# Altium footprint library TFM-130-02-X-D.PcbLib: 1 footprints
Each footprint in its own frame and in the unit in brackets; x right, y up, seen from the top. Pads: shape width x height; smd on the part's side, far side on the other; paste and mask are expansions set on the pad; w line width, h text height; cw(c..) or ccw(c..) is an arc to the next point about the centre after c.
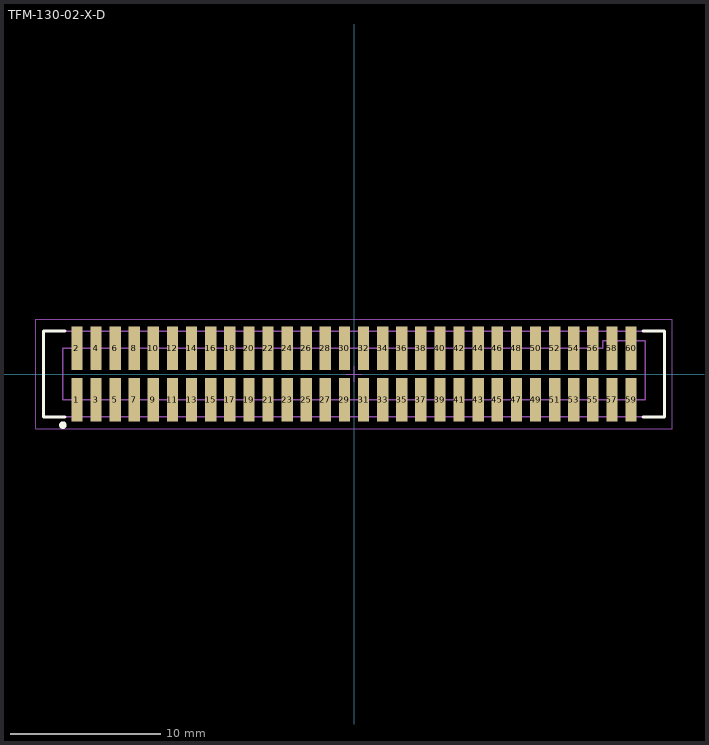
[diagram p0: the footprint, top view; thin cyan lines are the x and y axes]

## TFM-130-02-X-D [mm] "1.27mm pitch, 60 pin, terminal header; SMT"
height 5.72
pads (60):
  rect 0.75x2.9 smd mask+0: 1(-18.415,-1.714) 2(-18.415,1.714) 3(-17.145,-1.714) 4(-17.145,1.714) 5(-15.875,-1.714) 6(-15.875,1.714) 7(-14.605,-1.714) 8(-14.605,1.714) 9(-13.335,-1.714) 10(-13.335,1.714) 11(-12.065,-1.714) 12(-12.065,1.714) 13(-10.795,-1.714) 14(-10.795,1.714) 15(-9.525,-1.714) 16(-9.525,1.714) 17(-8.255,-1.714) 18(-8.255,1.714) 19(-6.985,-1.714) 20(-6.985,1.714) 21(-5.715,-1.714) 22(-5.715,1.714) 23(-4.445,-1.714) 24(-4.445,1.714) 25(-3.175,-1.714) 26(-3.175,1.714) 27(-1.905,-1.714) 28(-1.905,1.714) 29(-0.635,-1.714) 30(-0.635,1.714) 31(0.635,-1.714) 32(0.635,1.714) 33(1.905,-1.714) 34(1.905,1.714) 35(3.175,-1.714) 36(3.175,1.714) 37(4.445,-1.714) 38(4.445,1.714) 39(5.715,-1.714) 40(5.715,1.714) 41(6.985,-1.714) 42(6.985,1.714) 43(8.255,-1.714) 44(8.255,1.714) 45(9.525,-1.714) 46(9.525,1.714) 47(10.795,-1.714) 48(10.795,1.714) 49(12.065,-1.714) 50(12.065,1.714) 51(13.335,-1.714) 52(13.335,1.714) 53(14.605,-1.714) 54(14.605,1.714) 55(15.875,-1.714) 56(15.875,1.714) 57(17.145,-1.714) 58(17.145,1.714) 59(18.415,-1.714) 60(18.415,1.714)
Top Overlay:
  circle w0.25: c-19.35,-3.4 r0.125
  lines w0.2: -19.2,-2.85 -20.65,-2.85 -20.65,2.85 -19.2,2.85 ; 19.2,-2.85 20.65,-2.85 20.65,2.85 19.2,2.85
Mechanical 12:
  lines w0.001: -20.65,-2.85 20.65,-2.85 20.65,2.85 -20.65,2.85 -20.65,-2.85 ; -19.35,-1.7 19.35,-1.7 19.35,2.2 16.55,2.2 16.55,1.7 -19.35,1.7 -19.35,-1.7
Mechanical 13:
  circle w0.1: c-19.416,-3.35 r0.127
  lines w0.1: -20.65,-2.85 20.65,-2.85 20.65,2.85 -20.65,2.85 -20.65,-2.85 ; -19.35,-1.7 19.35,-1.7 19.35,2.2 16.55,2.2 16.55,1.7 -19.35,1.7 -19.35,-1.7
  text ".Designator" at 0,-0.127 h1.52
Mechanical 15:
  lines w0.05: -0.5,0 0.5,0 ; 0,-0.5 0,0.5 ; -21.15,-3.65 21.15,-3.65 21.15,3.65 -21.15,3.65 -21.15,-3.65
